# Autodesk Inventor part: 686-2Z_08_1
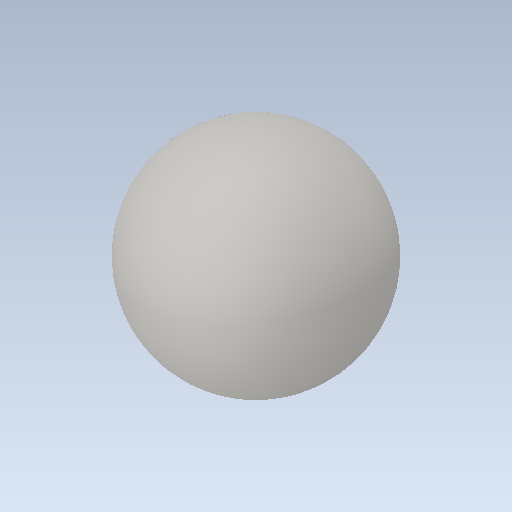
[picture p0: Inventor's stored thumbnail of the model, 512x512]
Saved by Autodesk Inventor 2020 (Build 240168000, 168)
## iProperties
Created: 2017-11
Part Number: 686-2Z_08_1
Material: Ogólny
Document SubType Name: Modeling
Designer: Tomasz
Density: 1 g/cm^3
Appearance: Domyślna
Sending System: SolidWorks 2017
Last Author: Tomasz
Last Saved: 2017-11-19
Source: 686-2Z_08_1
Author: Tomasz
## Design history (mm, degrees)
feature "Imported1"
node "Bryła1"
